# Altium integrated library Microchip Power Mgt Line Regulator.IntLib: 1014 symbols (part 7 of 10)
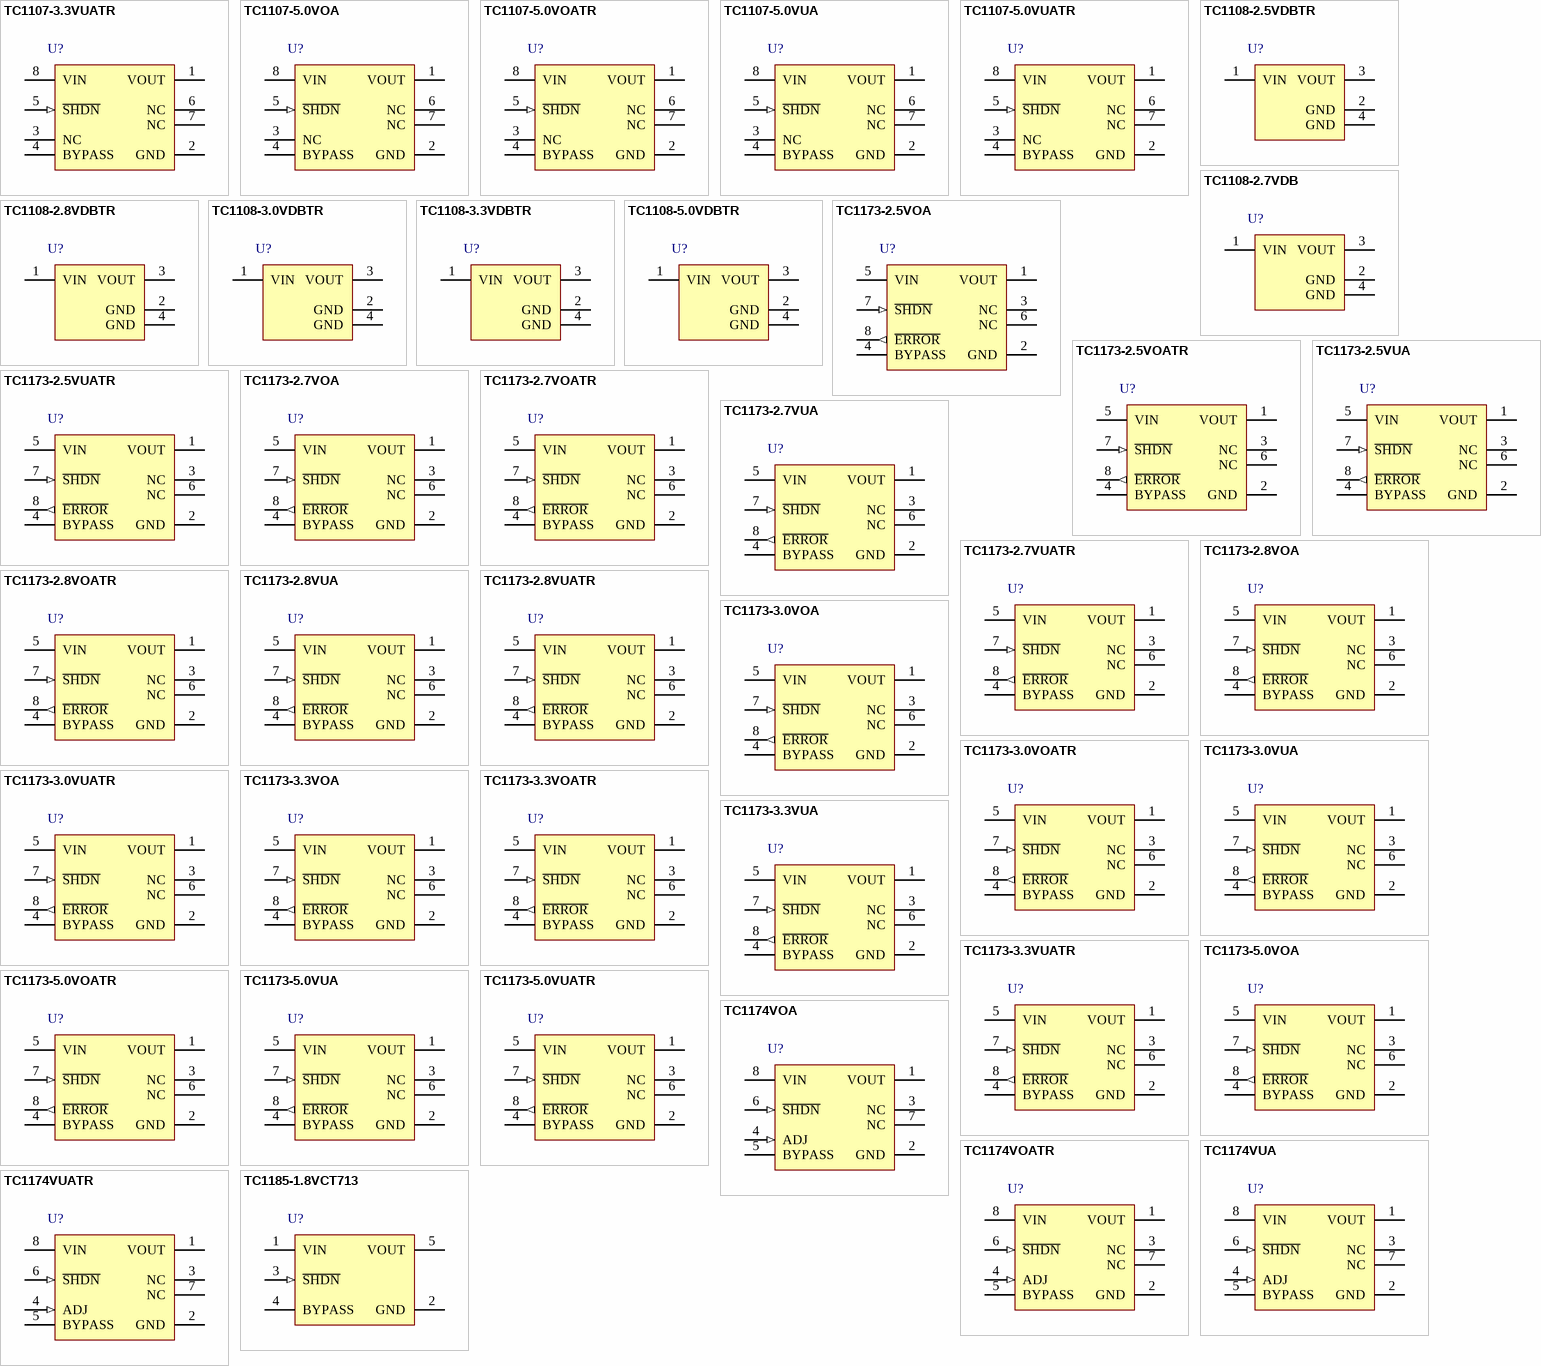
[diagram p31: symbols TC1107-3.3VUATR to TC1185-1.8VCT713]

## TC1173-3.0VOA
designator U?
300mA CMOS LDO with Shutdown Active-Low Error Output and Bypass, 8-Pin SOIC 150mil, Extended Temperature
footprint SOIC-OA8_N (SOIC, 8-Leads, Body 4.9x3.9mm, Pitch 1.27mm, IPC Medium Density)
footprint SOIC-OA8_L (SOIC, 8-Leads, Body 4.9x3.9mm, Pitch 1.27mm, IPC High Density)
footprint SOIC-OA8_M (SOIC, 8-Leads, Body 4.9x3.9mm, Pitch 1.27mm, IPC Low Density)
pins: 1 VOUT (power), 2 GND (power), 3 NC, 4 BYPASS, 5 VIN (power), 6 NC, 7 ~{SHDN} (in), 8 ~{ERROR} (out)

## TC1173-3.0VOATR
designator U?
300mA CMOS LDO with Shutdown Active-Low Error Output and Bypass, 8-Pin SOIC 150mil, Extended Temperature, Tape and Reel
footprint SOIC-OA8_N (SOIC, 8-Leads, Body 4.9x3.9mm, Pitch 1.27mm, IPC Medium Density)
footprint SOIC-OA8_L (SOIC, 8-Leads, Body 4.9x3.9mm, Pitch 1.27mm, IPC High Density)
footprint SOIC-OA8_M (SOIC, 8-Leads, Body 4.9x3.9mm, Pitch 1.27mm, IPC Low Density)
pins: 1 VOUT (power), 2 GND (power), 3 NC, 4 BYPASS, 5 VIN (power), 6 NC, 7 ~{SHDN} (in), 8 ~{ERROR} (out)

## TC1173-3.0VUA
designator U?
300mA CMOS LDO with Shutdown Active-Low Error Output and Bypass, 8-Pin MSOP, Extended Temperature
footprint MSOP-UA8_N (TSOP, 8-Leads, Body 3x3mm, Pitch 0.65mm, IPC Medium Density)
footprint MSOP-UA8_L (TSOP, 8-Leads, Body 3x3mm, Pitch 0.65mm, IPC High Density)
footprint MSOP-UA8_M (TSOP, 8-Leads, Body 3x3mm, Pitch 0.65mm, IPC Low Density)
pins: 1 VOUT (power), 2 GND (power), 3 NC, 4 BYPASS, 5 VIN (power), 6 NC, 7 ~{SHDN} (in), 8 ~{ERROR} (out)

## TC1173-3.0VUATR
designator U?
300mA CMOS LDO with Shutdown Active-Low Error Output and Bypass, 8-Pin MSOP, Extended Temperature, Tape and Reel
footprint MSOP-UA8_N (TSOP, 8-Leads, Body 3x3mm, Pitch 0.65mm, IPC Medium Density)
footprint MSOP-UA8_L (TSOP, 8-Leads, Body 3x3mm, Pitch 0.65mm, IPC High Density)
footprint MSOP-UA8_M (TSOP, 8-Leads, Body 3x3mm, Pitch 0.65mm, IPC Low Density)
pins: 1 VOUT (power), 2 GND (power), 3 NC, 4 BYPASS, 5 VIN (power), 6 NC, 7 ~{SHDN} (in), 8 ~{ERROR} (out)

## TC1173-3.3VOA
designator U?
300mA CMOS LDO with Shutdown Active-Low Error Output and Bypass, 8-Pin SOIC 150mil, Extended Temperature
footprint SOIC-OA8_N (SOIC, 8-Leads, Body 4.9x3.9mm, Pitch 1.27mm, IPC Medium Density)
footprint SOIC-OA8_L (SOIC, 8-Leads, Body 4.9x3.9mm, Pitch 1.27mm, IPC High Density)
footprint SOIC-OA8_M (SOIC, 8-Leads, Body 4.9x3.9mm, Pitch 1.27mm, IPC Low Density)
pins: 1 VOUT (power), 2 GND (power), 3 NC, 4 BYPASS, 5 VIN (power), 6 NC, 7 ~{SHDN} (in), 8 ~{ERROR} (out)

## TC1173-3.3VOATR
designator U?
300mA CMOS LDO with Shutdown Active-Low Error Output and Bypass, 8-Pin SOIC 150mil, Extended Temperature, Tape and Reel
footprint SOIC-OA8_N (SOIC, 8-Leads, Body 4.9x3.9mm, Pitch 1.27mm, IPC Medium Density)
footprint SOIC-OA8_L (SOIC, 8-Leads, Body 4.9x3.9mm, Pitch 1.27mm, IPC High Density)
footprint SOIC-OA8_M (SOIC, 8-Leads, Body 4.9x3.9mm, Pitch 1.27mm, IPC Low Density)
pins: 1 VOUT (power), 2 GND (power), 3 NC, 4 BYPASS, 5 VIN (power), 6 NC, 7 ~{SHDN} (in), 8 ~{ERROR} (out)

## TC1173-3.3VUA
designator U?
300mA CMOS LDO with Shutdown Active-Low Error Output and Bypass, 8-Pin MSOP, Extended Temperature
footprint MSOP-UA8_N (TSOP, 8-Leads, Body 3x3mm, Pitch 0.65mm, IPC Medium Density)
footprint MSOP-UA8_L (TSOP, 8-Leads, Body 3x3mm, Pitch 0.65mm, IPC High Density)
footprint MSOP-UA8_M (TSOP, 8-Leads, Body 3x3mm, Pitch 0.65mm, IPC Low Density)
pins: 1 VOUT (power), 2 GND (power), 3 NC, 4 BYPASS, 5 VIN (power), 6 NC, 7 ~{SHDN} (in), 8 ~{ERROR} (out)

## TC1173-3.3VUATR
designator U?
300mA CMOS LDO with Shutdown Active-Low Error Output and Bypass, 8-Pin MSOP, Extended Temperature, Tape and Reel
footprint MSOP-UA8_N (TSOP, 8-Leads, Body 3x3mm, Pitch 0.65mm, IPC Medium Density)
footprint MSOP-UA8_L (TSOP, 8-Leads, Body 3x3mm, Pitch 0.65mm, IPC High Density)
footprint MSOP-UA8_M (TSOP, 8-Leads, Body 3x3mm, Pitch 0.65mm, IPC Low Density)
pins: 1 VOUT (power), 2 GND (power), 3 NC, 4 BYPASS, 5 VIN (power), 6 NC, 7 ~{SHDN} (in), 8 ~{ERROR} (out)

## TC1173-5.0VOA
designator U?
300mA CMOS LDO with Shutdown Active-Low Error Output and Bypass, 8-Pin SOIC 150mil, Extended Temperature
footprint SOIC-OA8_N (SOIC, 8-Leads, Body 4.9x3.9mm, Pitch 1.27mm, IPC Medium Density)
footprint SOIC-OA8_L (SOIC, 8-Leads, Body 4.9x3.9mm, Pitch 1.27mm, IPC High Density)
footprint SOIC-OA8_M (SOIC, 8-Leads, Body 4.9x3.9mm, Pitch 1.27mm, IPC Low Density)
pins: 1 VOUT (power), 2 GND (power), 3 NC, 4 BYPASS, 5 VIN (power), 6 NC, 7 ~{SHDN} (in), 8 ~{ERROR} (out)

## TC1173-5.0VOATR
designator U?
300mA CMOS LDO with Shutdown Active-Low Error Output and Bypass, 8-Pin SOIC 150mil, Extended Temperature, Tape and Reel
footprint SOIC-OA8_N (SOIC, 8-Leads, Body 4.9x3.9mm, Pitch 1.27mm, IPC Medium Density)
footprint SOIC-OA8_L (SOIC, 8-Leads, Body 4.9x3.9mm, Pitch 1.27mm, IPC High Density)
footprint SOIC-OA8_M (SOIC, 8-Leads, Body 4.9x3.9mm, Pitch 1.27mm, IPC Low Density)
pins: 1 VOUT (power), 2 GND (power), 3 NC, 4 BYPASS, 5 VIN (power), 6 NC, 7 ~{SHDN} (in), 8 ~{ERROR} (out)

## TC1173-5.0VUA
designator U?
300mA CMOS LDO with Shutdown Active-Low Error Output and Bypass, 8-Pin MSOP, Extended Temperature
footprint MSOP-UA8_N (TSOP, 8-Leads, Body 3x3mm, Pitch 0.65mm, IPC Medium Density)
footprint MSOP-UA8_L (TSOP, 8-Leads, Body 3x3mm, Pitch 0.65mm, IPC High Density)
footprint MSOP-UA8_M (TSOP, 8-Leads, Body 3x3mm, Pitch 0.65mm, IPC Low Density)
pins: 1 VOUT (power), 2 GND (power), 3 NC, 4 BYPASS, 5 VIN (power), 6 NC, 7 ~{SHDN} (in), 8 ~{ERROR} (out)

## TC1173-5.0VUATR
designator U?
300mA CMOS LDO with Shutdown Active-Low Error Output and Bypass, 8-Pin MSOP, Extended Temperature, Tape and Reel
footprint MSOP-UA8_N (TSOP, 8-Leads, Body 3x3mm, Pitch 0.65mm, IPC Medium Density)
footprint MSOP-UA8_L (TSOP, 8-Leads, Body 3x3mm, Pitch 0.65mm, IPC High Density)
footprint MSOP-UA8_M (TSOP, 8-Leads, Body 3x3mm, Pitch 0.65mm, IPC Low Density)
pins: 1 VOUT (power), 2 GND (power), 3 NC, 4 BYPASS, 5 VIN (power), 6 NC, 7 ~{SHDN} (in), 8 ~{ERROR} (out)

## TC1174VOA
designator U?
300mA CMOS LDO with Shutdown and VREF Bypass, 8-Pin SOIC 150mil, Extended Temperature
footprint SOIC-OA8_N (SOIC, 8-Leads, Body 4.9x3.9mm, Pitch 1.27mm, IPC Medium Density)
footprint SOIC-OA8_L (SOIC, 8-Leads, Body 4.9x3.9mm, Pitch 1.27mm, IPC High Density)
footprint SOIC-OA8_M (SOIC, 8-Leads, Body 4.9x3.9mm, Pitch 1.27mm, IPC Low Density)
pins: 1 VOUT (power), 2 GND (power), 3 NC, 4 ADJ (in), 5 BYPASS, 6 ~{SHDN} (in), 7 NC, 8 VIN (power)

## TC1174VOATR
designator U?
300mA CMOS LDO with Shutdown and VREF Bypass, 8-Pin SOIC 150mil, Extended Temperature, Tape and Reel
footprint SOIC-OA8_N (SOIC, 8-Leads, Body 4.9x3.9mm, Pitch 1.27mm, IPC Medium Density)
footprint SOIC-OA8_L (SOIC, 8-Leads, Body 4.9x3.9mm, Pitch 1.27mm, IPC High Density)
footprint SOIC-OA8_M (SOIC, 8-Leads, Body 4.9x3.9mm, Pitch 1.27mm, IPC Low Density)
pins: 1 VOUT (power), 2 GND (power), 3 NC, 4 ADJ (in), 5 BYPASS, 6 ~{SHDN} (in), 7 NC, 8 VIN (power)

## TC1174VUA
designator U?
300mA CMOS LDO with Shutdown and VREF Bypass, 8-Pin MSOP, Extended Temperature
footprint MSOP-UA8_N (TSOP, 8-Leads, Body 3x3mm, Pitch 0.65mm, IPC Medium Density)
footprint MSOP-UA8_L (TSOP, 8-Leads, Body 3x3mm, Pitch 0.65mm, IPC High Density)
footprint MSOP-UA8_M (TSOP, 8-Leads, Body 3x3mm, Pitch 0.65mm, IPC Low Density)
pins: 1 VOUT (power), 2 GND (power), 3 NC, 4 ADJ (in), 5 BYPASS, 6 ~{SHDN} (in), 7 NC, 8 VIN (power)

## TC1174VUATR
designator U?
300mA CMOS LDO with Shutdown and VREF Bypass, 8-Pin MSOP, Extended Temperature, Tape and Reel
footprint MSOP-UA8_N (TSOP, 8-Leads, Body 3x3mm, Pitch 0.65mm, IPC Medium Density)
footprint MSOP-UA8_L (TSOP, 8-Leads, Body 3x3mm, Pitch 0.65mm, IPC High Density)
footprint MSOP-UA8_M (TSOP, 8-Leads, Body 3x3mm, Pitch 0.65mm, IPC Low Density)
pins: 1 VOUT (power), 2 GND (power), 3 NC, 4 ADJ (in), 5 BYPASS, 6 ~{SHDN} (in), 7 NC, 8 VIN (power)

## TC1185-1.8VCT713
designator U?
50 mA, 100 mA and 150 mA CMOS LDOs with Active-Low Shutdown and Reference Bypass, 5-Pin SOT-23, Extended Temperature, Tape and Reel
footprint SOT-23-CT5_N (SOT23, 5-Leads, Body 2.9x1.6mm, Pitch 0.95mm, Lead Span 2.7mm, IPC Medium Density)
footprint SOT-23-CT5_L (SOT23, 5-Leads, Body 2.9x1.6mm, Pitch 0.95mm, Lead Span 2.7mm, IPC High Density)
footprint SOT-23-CT5_M (SOT23, 5-Leads, Body 2.9x1.6mm, Pitch 0.95mm, Lead Span 2.7mm, IPC Low Density)
pins: 1 VIN (power), 2 GND (power), 3 ~{SHDN} (in), 4 BYPASS, 5 VOUT (power)

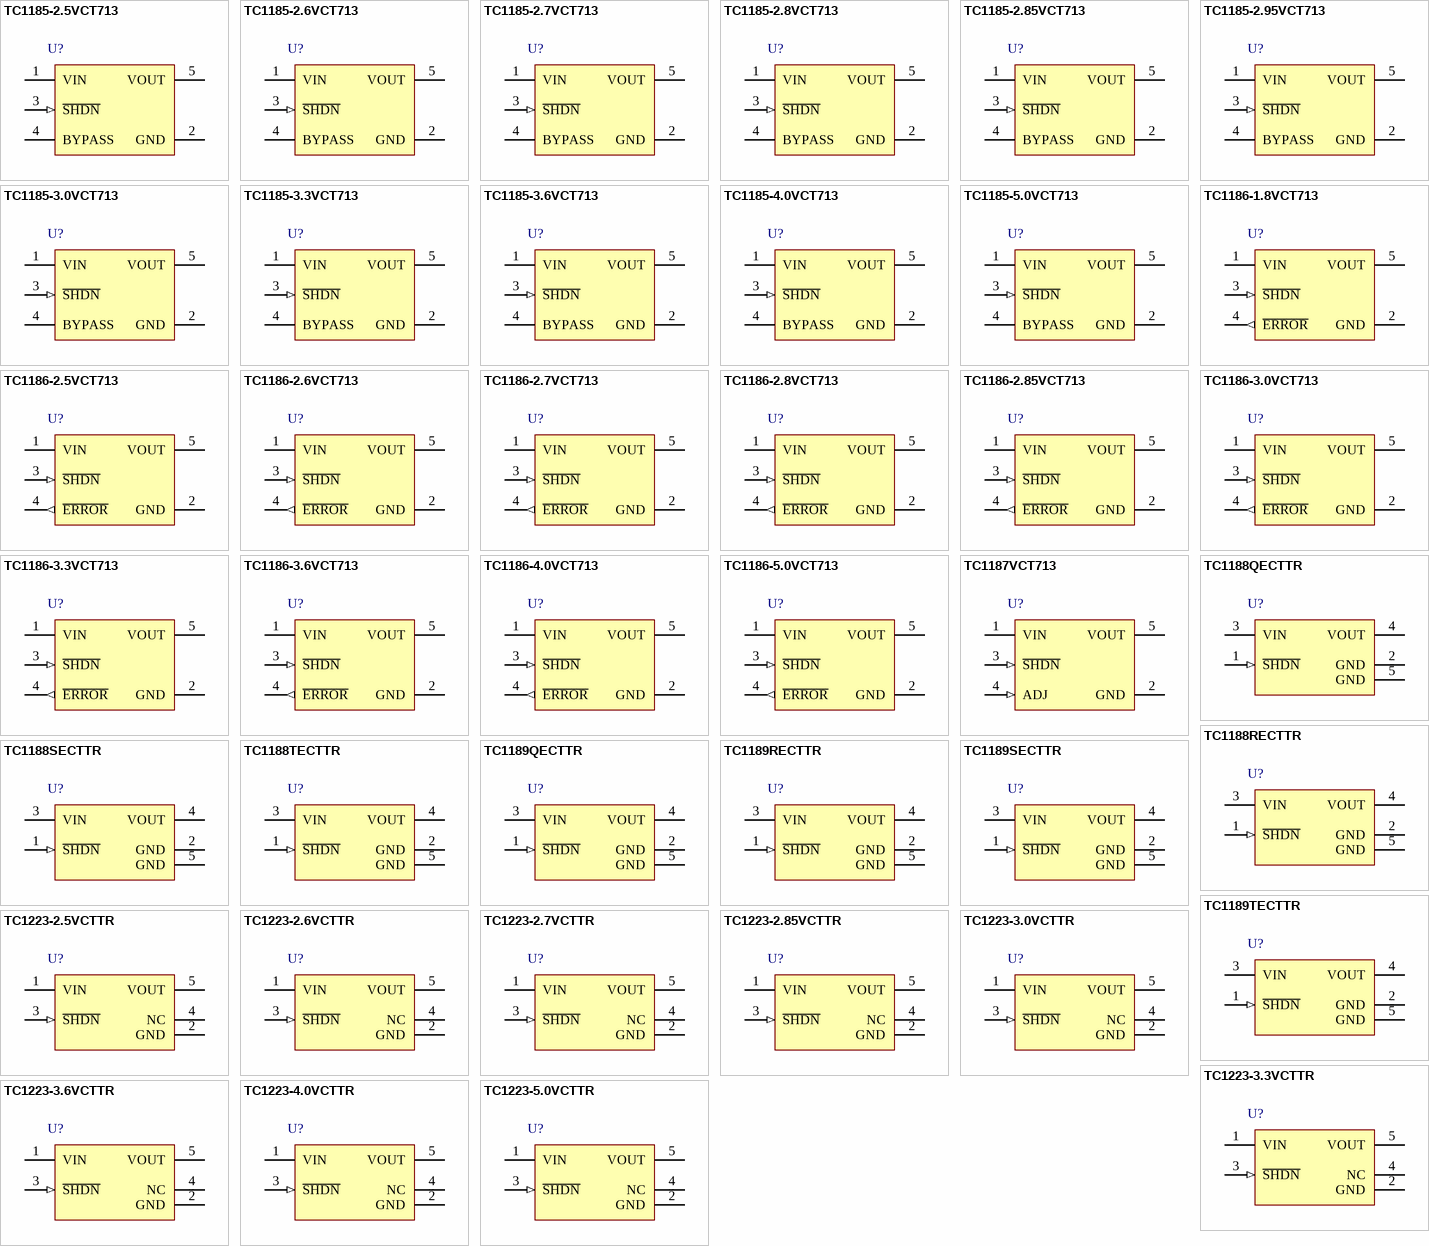
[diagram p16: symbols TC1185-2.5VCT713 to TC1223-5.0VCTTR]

## TC1185-2.5VCT713
designator U?
50 mA, 100 mA and 150 mA CMOS LDOs with Active-Low Shutdown and Reference Bypass, 5-Pin SOT-23, Extended Temperature, Tape and Reel
footprint SOT-23-CT5_N (SOT23, 5-Leads, Body 2.9x1.6mm, Pitch 0.95mm, Lead Span 2.7mm, IPC Medium Density)
footprint SOT-23-CT5_L (SOT23, 5-Leads, Body 2.9x1.6mm, Pitch 0.95mm, Lead Span 2.7mm, IPC High Density)
footprint SOT-23-CT5_M (SOT23, 5-Leads, Body 2.9x1.6mm, Pitch 0.95mm, Lead Span 2.7mm, IPC Low Density)
pins: 1 VIN (power), 2 GND (power), 3 ~{SHDN} (in), 4 BYPASS, 5 VOUT (power)

## TC1185-2.6VCT713
designator U?
50 mA, 100 mA and 150 mA CMOS LDOs with Active-Low Shutdown and Reference Bypass, 5-Pin SOT-23, Extended Temperature, Tape and Reel
footprint SOT-23-CT5_N (SOT23, 5-Leads, Body 2.9x1.6mm, Pitch 0.95mm, Lead Span 2.7mm, IPC Medium Density)
footprint SOT-23-CT5_L (SOT23, 5-Leads, Body 2.9x1.6mm, Pitch 0.95mm, Lead Span 2.7mm, IPC High Density)
footprint SOT-23-CT5_M (SOT23, 5-Leads, Body 2.9x1.6mm, Pitch 0.95mm, Lead Span 2.7mm, IPC Low Density)
pins: 1 VIN (power), 2 GND (power), 3 ~{SHDN} (in), 4 BYPASS, 5 VOUT (power)

## TC1185-2.7VCT713
designator U?
50 mA, 100 mA and 150 mA CMOS LDOs with Active-Low Shutdown and Reference Bypass, 5-Pin SOT-23, Extended Temperature, Tape and Reel
footprint SOT-23-CT5_N (SOT23, 5-Leads, Body 2.9x1.6mm, Pitch 0.95mm, Lead Span 2.7mm, IPC Medium Density)
footprint SOT-23-CT5_L (SOT23, 5-Leads, Body 2.9x1.6mm, Pitch 0.95mm, Lead Span 2.7mm, IPC High Density)
footprint SOT-23-CT5_M (SOT23, 5-Leads, Body 2.9x1.6mm, Pitch 0.95mm, Lead Span 2.7mm, IPC Low Density)
pins: 1 VIN (power), 2 GND (power), 3 ~{SHDN} (in), 4 BYPASS, 5 VOUT (power)

## TC1185-2.8VCT713
designator U?
50 mA, 100 mA and 150 mA CMOS LDOs with Active-Low Shutdown and Reference Bypass, 5-Pin SOT-23, Extended Temperature, Tape and Reel
footprint SOT-23-CT5_N (SOT23, 5-Leads, Body 2.9x1.6mm, Pitch 0.95mm, Lead Span 2.7mm, IPC Medium Density)
footprint SOT-23-CT5_L (SOT23, 5-Leads, Body 2.9x1.6mm, Pitch 0.95mm, Lead Span 2.7mm, IPC High Density)
footprint SOT-23-CT5_M (SOT23, 5-Leads, Body 2.9x1.6mm, Pitch 0.95mm, Lead Span 2.7mm, IPC Low Density)
pins: 1 VIN (power), 2 GND (power), 3 ~{SHDN} (in), 4 BYPASS, 5 VOUT (power)

## TC1185-2.85VCT713
designator U?
50 mA, 100 mA and 150 mA CMOS LDOs with Active-Low Shutdown and Reference Bypass, 5-Pin SOT-23, Extended Temperature, Tape and Reel
footprint SOT-23-CT5_N (SOT23, 5-Leads, Body 2.9x1.6mm, Pitch 0.95mm, Lead Span 2.7mm, IPC Medium Density)
footprint SOT-23-CT5_L (SOT23, 5-Leads, Body 2.9x1.6mm, Pitch 0.95mm, Lead Span 2.7mm, IPC High Density)
footprint SOT-23-CT5_M (SOT23, 5-Leads, Body 2.9x1.6mm, Pitch 0.95mm, Lead Span 2.7mm, IPC Low Density)
pins: 1 VIN (power), 2 GND (power), 3 ~{SHDN} (in), 4 BYPASS, 5 VOUT (power)

## TC1185-2.95VCT713
designator U?
50 mA, 100 mA and 150 mA CMOS LDOs with Active-Low Shutdown and Reference Bypass, 5-Pin SOT-23, Extended Temperature, Tape and Reel
footprint SOT-23-CT5_N (SOT23, 5-Leads, Body 2.9x1.6mm, Pitch 0.95mm, Lead Span 2.7mm, IPC Medium Density)
footprint SOT-23-CT5_L (SOT23, 5-Leads, Body 2.9x1.6mm, Pitch 0.95mm, Lead Span 2.7mm, IPC High Density)
footprint SOT-23-CT5_M (SOT23, 5-Leads, Body 2.9x1.6mm, Pitch 0.95mm, Lead Span 2.7mm, IPC Low Density)
pins: 1 VIN (power), 2 GND (power), 3 ~{SHDN} (in), 4 BYPASS, 5 VOUT (power)

## TC1185-3.0VCT713
designator U?
50 mA, 100 mA and 150 mA CMOS LDOs with Active-Low Shutdown and Reference Bypass, 5-Pin SOT-23, Extended Temperature, Tape and Reel
footprint SOT-23-CT5_N (SOT23, 5-Leads, Body 2.9x1.6mm, Pitch 0.95mm, Lead Span 2.7mm, IPC Medium Density)
footprint SOT-23-CT5_L (SOT23, 5-Leads, Body 2.9x1.6mm, Pitch 0.95mm, Lead Span 2.7mm, IPC High Density)
footprint SOT-23-CT5_M (SOT23, 5-Leads, Body 2.9x1.6mm, Pitch 0.95mm, Lead Span 2.7mm, IPC Low Density)
pins: 1 VIN (power), 2 GND (power), 3 ~{SHDN} (in), 4 BYPASS, 5 VOUT (power)

## TC1185-3.3VCT713
designator U?
50 mA, 100 mA and 150 mA CMOS LDOs with Active-Low Shutdown and Reference Bypass, 5-Pin SOT-23, Extended Temperature, Tape and Reel
footprint SOT-23-CT5_N (SOT23, 5-Leads, Body 2.9x1.6mm, Pitch 0.95mm, Lead Span 2.7mm, IPC Medium Density)
footprint SOT-23-CT5_L (SOT23, 5-Leads, Body 2.9x1.6mm, Pitch 0.95mm, Lead Span 2.7mm, IPC High Density)
footprint SOT-23-CT5_M (SOT23, 5-Leads, Body 2.9x1.6mm, Pitch 0.95mm, Lead Span 2.7mm, IPC Low Density)
pins: 1 VIN (power), 2 GND (power), 3 ~{SHDN} (in), 4 BYPASS, 5 VOUT (power)

## TC1185-3.6VCT713
designator U?
50 mA, 100 mA and 150 mA CMOS LDOs with Active-Low Shutdown and Reference Bypass, 5-Pin SOT-23, Extended Temperature, Tape and Reel
footprint SOT-23-CT5_N (SOT23, 5-Leads, Body 2.9x1.6mm, Pitch 0.95mm, Lead Span 2.7mm, IPC Medium Density)
footprint SOT-23-CT5_L (SOT23, 5-Leads, Body 2.9x1.6mm, Pitch 0.95mm, Lead Span 2.7mm, IPC High Density)
footprint SOT-23-CT5_M (SOT23, 5-Leads, Body 2.9x1.6mm, Pitch 0.95mm, Lead Span 2.7mm, IPC Low Density)
pins: 1 VIN (power), 2 GND (power), 3 ~{SHDN} (in), 4 BYPASS, 5 VOUT (power)

## TC1185-4.0VCT713
designator U?
50 mA, 100 mA and 150 mA CMOS LDOs with Active-Low Shutdown and Reference Bypass, 5-Pin SOT-23, Extended Temperature, Tape and Reel
footprint SOT-23-CT5_N (SOT23, 5-Leads, Body 2.9x1.6mm, Pitch 0.95mm, Lead Span 2.7mm, IPC Medium Density)
footprint SOT-23-CT5_L (SOT23, 5-Leads, Body 2.9x1.6mm, Pitch 0.95mm, Lead Span 2.7mm, IPC High Density)
footprint SOT-23-CT5_M (SOT23, 5-Leads, Body 2.9x1.6mm, Pitch 0.95mm, Lead Span 2.7mm, IPC Low Density)
pins: 1 VIN (power), 2 GND (power), 3 ~{SHDN} (in), 4 BYPASS, 5 VOUT (power)

## TC1185-5.0VCT713
designator U?
50 mA, 100 mA and 150 mA CMOS LDOs with Active-Low Shutdown and Reference Bypass, 5-Pin SOT-23, Extended Temperature, Tape and Reel
footprint SOT-23-CT5_N (SOT23, 5-Leads, Body 2.9x1.6mm, Pitch 0.95mm, Lead Span 2.7mm, IPC Medium Density)
footprint SOT-23-CT5_L (SOT23, 5-Leads, Body 2.9x1.6mm, Pitch 0.95mm, Lead Span 2.7mm, IPC High Density)
footprint SOT-23-CT5_M (SOT23, 5-Leads, Body 2.9x1.6mm, Pitch 0.95mm, Lead Span 2.7mm, IPC Low Density)
pins: 1 VIN (power), 2 GND (power), 3 ~{SHDN} (in), 4 BYPASS, 5 VOUT (power)

## TC1186-1.8VCT713
designator U?
50 mA, 100 mA and 150 mA CMOS LDOs with Shutdown and Active-Low Error Output, 5-Pin SOT-23, Extended Temperature, Tape and Reel
footprint SOT-23-CT5_N (SOT23, 5-Leads, Body 2.9x1.6mm, Pitch 0.95mm, Lead Span 2.7mm, IPC Medium Density)
footprint SOT-23-CT5_L (SOT23, 5-Leads, Body 2.9x1.6mm, Pitch 0.95mm, Lead Span 2.7mm, IPC High Density)
footprint SOT-23-CT5_M (SOT23, 5-Leads, Body 2.9x1.6mm, Pitch 0.95mm, Lead Span 2.7mm, IPC Low Density)
pins: 1 VIN (power), 2 GND (power), 3 ~{SHDN} (in), 4 ~{ERROR} (out), 5 VOUT (power)

## TC1186-2.5VCT713
designator U?
50 mA, 100 mA and 150 mA CMOS LDOs with Shutdown and Active-Low Error Output, 5-Pin SOT-23, Extended Temperature, Tape and Reel
footprint SOT-23-CT5_N (SOT23, 5-Leads, Body 2.9x1.6mm, Pitch 0.95mm, Lead Span 2.7mm, IPC Medium Density)
footprint SOT-23-CT5_L (SOT23, 5-Leads, Body 2.9x1.6mm, Pitch 0.95mm, Lead Span 2.7mm, IPC High Density)
footprint SOT-23-CT5_M (SOT23, 5-Leads, Body 2.9x1.6mm, Pitch 0.95mm, Lead Span 2.7mm, IPC Low Density)
pins: 1 VIN (power), 2 GND (power), 3 ~{SHDN} (in), 4 ~{ERROR} (out), 5 VOUT (power)

## TC1186-2.6VCT713
designator U?
50 mA, 100 mA and 150 mA CMOS LDOs with Shutdown and Active-Low Error Output, 5-Pin SOT-23, Extended Temperature, Tape and Reel
footprint SOT-23-CT5_N (SOT23, 5-Leads, Body 2.9x1.6mm, Pitch 0.95mm, Lead Span 2.7mm, IPC Medium Density)
footprint SOT-23-CT5_L (SOT23, 5-Leads, Body 2.9x1.6mm, Pitch 0.95mm, Lead Span 2.7mm, IPC High Density)
footprint SOT-23-CT5_M (SOT23, 5-Leads, Body 2.9x1.6mm, Pitch 0.95mm, Lead Span 2.7mm, IPC Low Density)
pins: 1 VIN (power), 2 GND (power), 3 ~{SHDN} (in), 4 ~{ERROR} (out), 5 VOUT (power)

## TC1186-2.7VCT713
designator U?
50 mA, 100 mA and 150 mA CMOS LDOs with Shutdown and Active-Low Error Output, 5-Pin SOT-23, Extended Temperature, Tape and Reel
footprint SOT-23-CT5_N (SOT23, 5-Leads, Body 2.9x1.6mm, Pitch 0.95mm, Lead Span 2.7mm, IPC Medium Density)
footprint SOT-23-CT5_L (SOT23, 5-Leads, Body 2.9x1.6mm, Pitch 0.95mm, Lead Span 2.7mm, IPC High Density)
footprint SOT-23-CT5_M (SOT23, 5-Leads, Body 2.9x1.6mm, Pitch 0.95mm, Lead Span 2.7mm, IPC Low Density)
pins: 1 VIN (power), 2 GND (power), 3 ~{SHDN} (in), 4 ~{ERROR} (out), 5 VOUT (power)

## TC1186-2.8VCT713
designator U?
50 mA, 100 mA and 150 mA CMOS LDOs with Shutdown and Active-Low Error Output, 5-Pin SOT-23, Extended Temperature, Tape and Reel
footprint SOT-23-CT5_N (SOT23, 5-Leads, Body 2.9x1.6mm, Pitch 0.95mm, Lead Span 2.7mm, IPC Medium Density)
footprint SOT-23-CT5_L (SOT23, 5-Leads, Body 2.9x1.6mm, Pitch 0.95mm, Lead Span 2.7mm, IPC High Density)
footprint SOT-23-CT5_M (SOT23, 5-Leads, Body 2.9x1.6mm, Pitch 0.95mm, Lead Span 2.7mm, IPC Low Density)
pins: 1 VIN (power), 2 GND (power), 3 ~{SHDN} (in), 4 ~{ERROR} (out), 5 VOUT (power)

## TC1186-2.85VCT713
designator U?
50 mA, 100 mA and 150 mA CMOS LDOs with Shutdown and Active-Low Error Output, 5-Pin SOT-23, Extended Temperature, Tape and Reel
footprint SOT-23-CT5_N (SOT23, 5-Leads, Body 2.9x1.6mm, Pitch 0.95mm, Lead Span 2.7mm, IPC Medium Density)
footprint SOT-23-CT5_L (SOT23, 5-Leads, Body 2.9x1.6mm, Pitch 0.95mm, Lead Span 2.7mm, IPC High Density)
footprint SOT-23-CT5_M (SOT23, 5-Leads, Body 2.9x1.6mm, Pitch 0.95mm, Lead Span 2.7mm, IPC Low Density)
pins: 1 VIN (power), 2 GND (power), 3 ~{SHDN} (in), 4 ~{ERROR} (out), 5 VOUT (power)

## TC1186-3.0VCT713
designator U?
50 mA, 100 mA and 150 mA CMOS LDOs with Shutdown and Active-Low Error Output, 5-Pin SOT-23, Extended Temperature, Tape and Reel
footprint SOT-23-CT5_N (SOT23, 5-Leads, Body 2.9x1.6mm, Pitch 0.95mm, Lead Span 2.7mm, IPC Medium Density)
footprint SOT-23-CT5_L (SOT23, 5-Leads, Body 2.9x1.6mm, Pitch 0.95mm, Lead Span 2.7mm, IPC High Density)
footprint SOT-23-CT5_M (SOT23, 5-Leads, Body 2.9x1.6mm, Pitch 0.95mm, Lead Span 2.7mm, IPC Low Density)
pins: 1 VIN (power), 2 GND (power), 3 ~{SHDN} (in), 4 ~{ERROR} (out), 5 VOUT (power)

## TC1186-3.3VCT713
designator U?
50 mA, 100 mA and 150 mA CMOS LDOs with Shutdown and Active-Low Error Output, 5-Pin SOT-23, Extended Temperature, Tape and Reel
footprint SOT-23-CT5_N (SOT23, 5-Leads, Body 2.9x1.6mm, Pitch 0.95mm, Lead Span 2.7mm, IPC Medium Density)
footprint SOT-23-CT5_L (SOT23, 5-Leads, Body 2.9x1.6mm, Pitch 0.95mm, Lead Span 2.7mm, IPC High Density)
footprint SOT-23-CT5_M (SOT23, 5-Leads, Body 2.9x1.6mm, Pitch 0.95mm, Lead Span 2.7mm, IPC Low Density)
pins: 1 VIN (power), 2 GND (power), 3 ~{SHDN} (in), 4 ~{ERROR} (out), 5 VOUT (power)

## TC1186-3.6VCT713
designator U?
50 mA, 100 mA and 150 mA CMOS LDOs with Shutdown and Active-Low Error Output, 5-Pin SOT-23, Extended Temperature, Tape and Reel
footprint SOT-23-CT5_N (SOT23, 5-Leads, Body 2.9x1.6mm, Pitch 0.95mm, Lead Span 2.7mm, IPC Medium Density)
footprint SOT-23-CT5_L (SOT23, 5-Leads, Body 2.9x1.6mm, Pitch 0.95mm, Lead Span 2.7mm, IPC High Density)
footprint SOT-23-CT5_M (SOT23, 5-Leads, Body 2.9x1.6mm, Pitch 0.95mm, Lead Span 2.7mm, IPC Low Density)
pins: 1 VIN (power), 2 GND (power), 3 ~{SHDN} (in), 4 ~{ERROR} (out), 5 VOUT (power)

## TC1186-4.0VCT713
designator U?
50 mA, 100 mA and 150 mA CMOS LDOs with Shutdown and Active-Low Error Output, 5-Pin SOT-23, Extended Temperature, Tape and Reel
footprint SOT-23-CT5_N (SOT23, 5-Leads, Body 2.9x1.6mm, Pitch 0.95mm, Lead Span 2.7mm, IPC Medium Density)
footprint SOT-23-CT5_L (SOT23, 5-Leads, Body 2.9x1.6mm, Pitch 0.95mm, Lead Span 2.7mm, IPC High Density)
footprint SOT-23-CT5_M (SOT23, 5-Leads, Body 2.9x1.6mm, Pitch 0.95mm, Lead Span 2.7mm, IPC Low Density)
pins: 1 VIN (power), 2 GND (power), 3 ~{SHDN} (in), 4 ~{ERROR} (out), 5 VOUT (power)

## TC1186-5.0VCT713
designator U?
50 mA, 100 mA and 150 mA CMOS LDOs with Shutdown and Active-Low Error Output, 5-Pin SOT-23, Extended Temperature, Tape and Reel
footprint SOT-23-CT5_N (SOT23, 5-Leads, Body 2.9x1.6mm, Pitch 0.95mm, Lead Span 2.7mm, IPC Medium Density)
footprint SOT-23-CT5_L (SOT23, 5-Leads, Body 2.9x1.6mm, Pitch 0.95mm, Lead Span 2.7mm, IPC High Density)
footprint SOT-23-CT5_M (SOT23, 5-Leads, Body 2.9x1.6mm, Pitch 0.95mm, Lead Span 2.7mm, IPC Low Density)
pins: 1 VIN (power), 2 GND (power), 3 ~{SHDN} (in), 4 ~{ERROR} (out), 5 VOUT (power)

## TC1187VCT713
designator U?
50mA, 100mA and 150mA Adjustable CMOS LDOs with Shutdown, 5-Pin SOT-23, Extended Temperature, Tape and Reel
footprint SOT-23-CT5_N (SOT23, 5-Leads, Body 2.9x1.6mm, Pitch 0.95mm, Lead Span 2.7mm, IPC Medium Density)
footprint SOT-23-CT5_L (SOT23, 5-Leads, Body 2.9x1.6mm, Pitch 0.95mm, Lead Span 2.7mm, IPC High Density)
footprint SOT-23-CT5_M (SOT23, 5-Leads, Body 2.9x1.6mm, Pitch 0.95mm, Lead Span 2.7mm, IPC Low Density)
pins: 1 VIN (power), 2 GND (power), 3 ~{SHDN} (in), 4 ADJ (in), 5 VOUT (power)

## TC1188QECTTR
designator U?
MAX8863/64 Pin Compatible, Low Dropout, 120 mA Linear Regulators, 5-Pin SOT-23, Industrial Temperature, Tape and Reel
footprint SOT-23-CT5_N (SOT23, 5-Leads, Body 2.9x1.6mm, Pitch 0.95mm, Lead Span 2.7mm, IPC Medium Density)
footprint SOT-23-CT5_L (SOT23, 5-Leads, Body 2.9x1.6mm, Pitch 0.95mm, Lead Span 2.7mm, IPC High Density)
footprint SOT-23-CT5_M (SOT23, 5-Leads, Body 2.9x1.6mm, Pitch 0.95mm, Lead Span 2.7mm, IPC Low Density)
pins: 1 ~{SHDN} (in), 2 GND (power), 3 VIN (power), 4 VOUT (power), 5 GND (power)

## TC1188RECTTR
designator U?
MAX8863/64 Pin Compatible, Low Dropout, 120 mA Linear Regulators, 5-Pin SOT-23, Industrial Temperature, Tape and Reel
footprint SOT-23-CT5_N (SOT23, 5-Leads, Body 2.9x1.6mm, Pitch 0.95mm, Lead Span 2.7mm, IPC Medium Density)
footprint SOT-23-CT5_L (SOT23, 5-Leads, Body 2.9x1.6mm, Pitch 0.95mm, Lead Span 2.7mm, IPC High Density)
footprint SOT-23-CT5_M (SOT23, 5-Leads, Body 2.9x1.6mm, Pitch 0.95mm, Lead Span 2.7mm, IPC Low Density)
pins: 1 ~{SHDN} (in), 2 GND (power), 3 VIN (power), 4 VOUT (power), 5 GND (power)

## TC1188SECTTR
designator U?
MAX8863/64 Pin Compatible, Low Dropout, 120 mA Linear Regulators, 5-Pin SOT-23, Industrial Temperature, Tape and Reel
footprint SOT-23-CT5_N (SOT23, 5-Leads, Body 2.9x1.6mm, Pitch 0.95mm, Lead Span 2.7mm, IPC Medium Density)
footprint SOT-23-CT5_L (SOT23, 5-Leads, Body 2.9x1.6mm, Pitch 0.95mm, Lead Span 2.7mm, IPC High Density)
footprint SOT-23-CT5_M (SOT23, 5-Leads, Body 2.9x1.6mm, Pitch 0.95mm, Lead Span 2.7mm, IPC Low Density)
pins: 1 ~{SHDN} (in), 2 GND (power), 3 VIN (power), 4 VOUT (power), 5 GND (power)

## TC1188TECTTR
designator U?
MAX8863/64 Pin Compatible, Low Dropout, 120 mA Linear Regulators, 5-Pin SOT-23, Industrial Temperature, Tape and Reel
footprint SOT-23-CT5_N (SOT23, 5-Leads, Body 2.9x1.6mm, Pitch 0.95mm, Lead Span 2.7mm, IPC Medium Density)
footprint SOT-23-CT5_L (SOT23, 5-Leads, Body 2.9x1.6mm, Pitch 0.95mm, Lead Span 2.7mm, IPC High Density)
footprint SOT-23-CT5_M (SOT23, 5-Leads, Body 2.9x1.6mm, Pitch 0.95mm, Lead Span 2.7mm, IPC Low Density)
pins: 1 ~{SHDN} (in), 2 GND (power), 3 VIN (power), 4 VOUT (power), 5 GND (power)

## TC1189QECTTR
designator U?
MAX8863/64 Pin Compatible, Low Dropout, 120 mA Linear Regulators, 5-Pin SOT-23, Industrial Temperature, Tape and Reel
footprint SOT-23-CT5_N (SOT23, 5-Leads, Body 2.9x1.6mm, Pitch 0.95mm, Lead Span 2.7mm, IPC Medium Density)
footprint SOT-23-CT5_L (SOT23, 5-Leads, Body 2.9x1.6mm, Pitch 0.95mm, Lead Span 2.7mm, IPC High Density)
footprint SOT-23-CT5_M (SOT23, 5-Leads, Body 2.9x1.6mm, Pitch 0.95mm, Lead Span 2.7mm, IPC Low Density)
pins: 1 ~{SHDN} (in), 2 GND (power), 3 VIN (power), 4 VOUT (power), 5 GND (power)

## TC1189RECTTR
designator U?
MAX8863/64 Pin Compatible, Low Dropout, 120 mA Linear Regulators, 5-Pin SOT-23, Industrial Temperature, Tape and Reel
footprint SOT-23-CT5_N (SOT23, 5-Leads, Body 2.9x1.6mm, Pitch 0.95mm, Lead Span 2.7mm, IPC Medium Density)
footprint SOT-23-CT5_L (SOT23, 5-Leads, Body 2.9x1.6mm, Pitch 0.95mm, Lead Span 2.7mm, IPC High Density)
footprint SOT-23-CT5_M (SOT23, 5-Leads, Body 2.9x1.6mm, Pitch 0.95mm, Lead Span 2.7mm, IPC Low Density)
pins: 1 ~{SHDN} (in), 2 GND (power), 3 VIN (power), 4 VOUT (power), 5 GND (power)

## TC1189SECTTR
designator U?
MAX8863/64 Pin Compatible, Low Dropout, 120 mA Linear Regulators, 5-Pin SOT-23, Industrial Temperature, Tape and Reel
footprint SOT-23-CT5_N (SOT23, 5-Leads, Body 2.9x1.6mm, Pitch 0.95mm, Lead Span 2.7mm, IPC Medium Density)
footprint SOT-23-CT5_L (SOT23, 5-Leads, Body 2.9x1.6mm, Pitch 0.95mm, Lead Span 2.7mm, IPC High Density)
footprint SOT-23-CT5_M (SOT23, 5-Leads, Body 2.9x1.6mm, Pitch 0.95mm, Lead Span 2.7mm, IPC Low Density)
pins: 1 ~{SHDN} (in), 2 GND (power), 3 VIN (power), 4 VOUT (power), 5 GND (power)

## TC1189TECTTR
designator U?
MAX8863/64 Pin Compatible, Low Dropout, 120 mA Linear Regulators, 5-Pin SOT-23, Industrial Temperature, Tape and Reel
footprint SOT-23-CT5_N (SOT23, 5-Leads, Body 2.9x1.6mm, Pitch 0.95mm, Lead Span 2.7mm, IPC Medium Density)
footprint SOT-23-CT5_L (SOT23, 5-Leads, Body 2.9x1.6mm, Pitch 0.95mm, Lead Span 2.7mm, IPC High Density)
footprint SOT-23-CT5_M (SOT23, 5-Leads, Body 2.9x1.6mm, Pitch 0.95mm, Lead Span 2.7mm, IPC Low Density)
pins: 1 ~{SHDN} (in), 2 GND (power), 3 VIN (power), 4 VOUT (power), 5 GND (power)

## TC1223-2.5VCTTR
designator U?
50mA and 100mA CMOS LDOs with Shutdown, 5-Pin SOT-23, Extended Temperature, Tape and Reel
footprint SOT-23-CT5_N (SOT23, 5-Leads, Body 2.9x1.6mm, Pitch 0.95mm, Lead Span 2.7mm, IPC Medium Density)
footprint SOT-23-CT5_L (SOT23, 5-Leads, Body 2.9x1.6mm, Pitch 0.95mm, Lead Span 2.7mm, IPC High Density)
footprint SOT-23-CT5_M (SOT23, 5-Leads, Body 2.9x1.6mm, Pitch 0.95mm, Lead Span 2.7mm, IPC Low Density)
pins: 1 VIN (power), 2 GND (power), 3 ~{SHDN} (in), 4 NC, 5 VOUT (power)

## TC1223-2.6VCTTR
designator U?
50mA and 100mA CMOS LDOs with Shutdown, 5-Pin SOT-23, Extended Temperature, Tape and Reel
footprint SOT-23-CT5_N (SOT23, 5-Leads, Body 2.9x1.6mm, Pitch 0.95mm, Lead Span 2.7mm, IPC Medium Density)
footprint SOT-23-CT5_L (SOT23, 5-Leads, Body 2.9x1.6mm, Pitch 0.95mm, Lead Span 2.7mm, IPC High Density)
footprint SOT-23-CT5_M (SOT23, 5-Leads, Body 2.9x1.6mm, Pitch 0.95mm, Lead Span 2.7mm, IPC Low Density)
pins: 1 VIN (power), 2 GND (power), 3 ~{SHDN} (in), 4 NC, 5 VOUT (power)

## TC1223-2.7VCTTR
designator U?
50mA and 100mA CMOS LDOs with Shutdown, 5-Pin SOT-23, Extended Temperature, Tape and Reel
footprint SOT-23-CT5_N (SOT23, 5-Leads, Body 2.9x1.6mm, Pitch 0.95mm, Lead Span 2.7mm, IPC Medium Density)
footprint SOT-23-CT5_L (SOT23, 5-Leads, Body 2.9x1.6mm, Pitch 0.95mm, Lead Span 2.7mm, IPC High Density)
footprint SOT-23-CT5_M (SOT23, 5-Leads, Body 2.9x1.6mm, Pitch 0.95mm, Lead Span 2.7mm, IPC Low Density)
pins: 1 VIN (power), 2 GND (power), 3 ~{SHDN} (in), 4 NC, 5 VOUT (power)

## TC1223-2.85VCTTR
designator U?
50mA and 100mA CMOS LDOs with Shutdown, 5-Pin SOT-23, Extended Temperature, Tape and Reel
footprint SOT-23-CT5_N (SOT23, 5-Leads, Body 2.9x1.6mm, Pitch 0.95mm, Lead Span 2.7mm, IPC Medium Density)
footprint SOT-23-CT5_L (SOT23, 5-Leads, Body 2.9x1.6mm, Pitch 0.95mm, Lead Span 2.7mm, IPC High Density)
footprint SOT-23-CT5_M (SOT23, 5-Leads, Body 2.9x1.6mm, Pitch 0.95mm, Lead Span 2.7mm, IPC Low Density)
pins: 1 VIN (power), 2 GND (power), 3 ~{SHDN} (in), 4 NC, 5 VOUT (power)

## TC1223-3.0VCTTR
designator U?
50mA and 100mA CMOS LDOs with Shutdown, 5-Pin SOT-23, Extended Temperature, Tape and Reel
footprint SOT-23-CT5_N (SOT23, 5-Leads, Body 2.9x1.6mm, Pitch 0.95mm, Lead Span 2.7mm, IPC Medium Density)
footprint SOT-23-CT5_L (SOT23, 5-Leads, Body 2.9x1.6mm, Pitch 0.95mm, Lead Span 2.7mm, IPC High Density)
footprint SOT-23-CT5_M (SOT23, 5-Leads, Body 2.9x1.6mm, Pitch 0.95mm, Lead Span 2.7mm, IPC Low Density)
pins: 1 VIN (power), 2 GND (power), 3 ~{SHDN} (in), 4 NC, 5 VOUT (power)

## TC1223-3.3VCTTR
designator U?
50mA and 100mA CMOS LDOs with Shutdown, 5-Pin SOT-23, Extended Temperature, Tape and Reel
footprint SOT-23-CT5_N (SOT23, 5-Leads, Body 2.9x1.6mm, Pitch 0.95mm, Lead Span 2.7mm, IPC Medium Density)
footprint SOT-23-CT5_L (SOT23, 5-Leads, Body 2.9x1.6mm, Pitch 0.95mm, Lead Span 2.7mm, IPC High Density)
footprint SOT-23-CT5_M (SOT23, 5-Leads, Body 2.9x1.6mm, Pitch 0.95mm, Lead Span 2.7mm, IPC Low Density)
pins: 1 VIN (power), 2 GND (power), 3 ~{SHDN} (in), 4 NC, 5 VOUT (power)

## TC1223-3.6VCTTR
designator U?
50mA and 100mA CMOS LDOs with Shutdown, 5-Pin SOT-23, Extended Temperature, Tape and Reel
footprint SOT-23-CT5_N (SOT23, 5-Leads, Body 2.9x1.6mm, Pitch 0.95mm, Lead Span 2.7mm, IPC Medium Density)
footprint SOT-23-CT5_L (SOT23, 5-Leads, Body 2.9x1.6mm, Pitch 0.95mm, Lead Span 2.7mm, IPC High Density)
footprint SOT-23-CT5_M (SOT23, 5-Leads, Body 2.9x1.6mm, Pitch 0.95mm, Lead Span 2.7mm, IPC Low Density)
pins: 1 VIN (power), 2 GND (power), 3 ~{SHDN} (in), 4 NC, 5 VOUT (power)

## TC1223-4.0VCTTR
designator U?
50mA and 100mA CMOS LDOs with Shutdown, 5-Pin SOT-23, Extended Temperature, Tape and Reel
footprint SOT-23-CT5_N (SOT23, 5-Leads, Body 2.9x1.6mm, Pitch 0.95mm, Lead Span 2.7mm, IPC Medium Density)
footprint SOT-23-CT5_L (SOT23, 5-Leads, Body 2.9x1.6mm, Pitch 0.95mm, Lead Span 2.7mm, IPC High Density)
footprint SOT-23-CT5_M (SOT23, 5-Leads, Body 2.9x1.6mm, Pitch 0.95mm, Lead Span 2.7mm, IPC Low Density)
pins: 1 VIN (power), 2 GND (power), 3 ~{SHDN} (in), 4 NC, 5 VOUT (power)

## TC1223-5.0VCTTR
designator U?
50mA and 100mA CMOS LDOs with Shutdown, 5-Pin SOT-23, Extended Temperature, Tape and Reel
footprint SOT-23-CT5_N (SOT23, 5-Leads, Body 2.9x1.6mm, Pitch 0.95mm, Lead Span 2.7mm, IPC Medium Density)
footprint SOT-23-CT5_L (SOT23, 5-Leads, Body 2.9x1.6mm, Pitch 0.95mm, Lead Span 2.7mm, IPC High Density)
footprint SOT-23-CT5_M (SOT23, 5-Leads, Body 2.9x1.6mm, Pitch 0.95mm, Lead Span 2.7mm, IPC Low Density)
pins: 1 VIN (power), 2 GND (power), 3 ~{SHDN} (in), 4 NC, 5 VOUT (power)

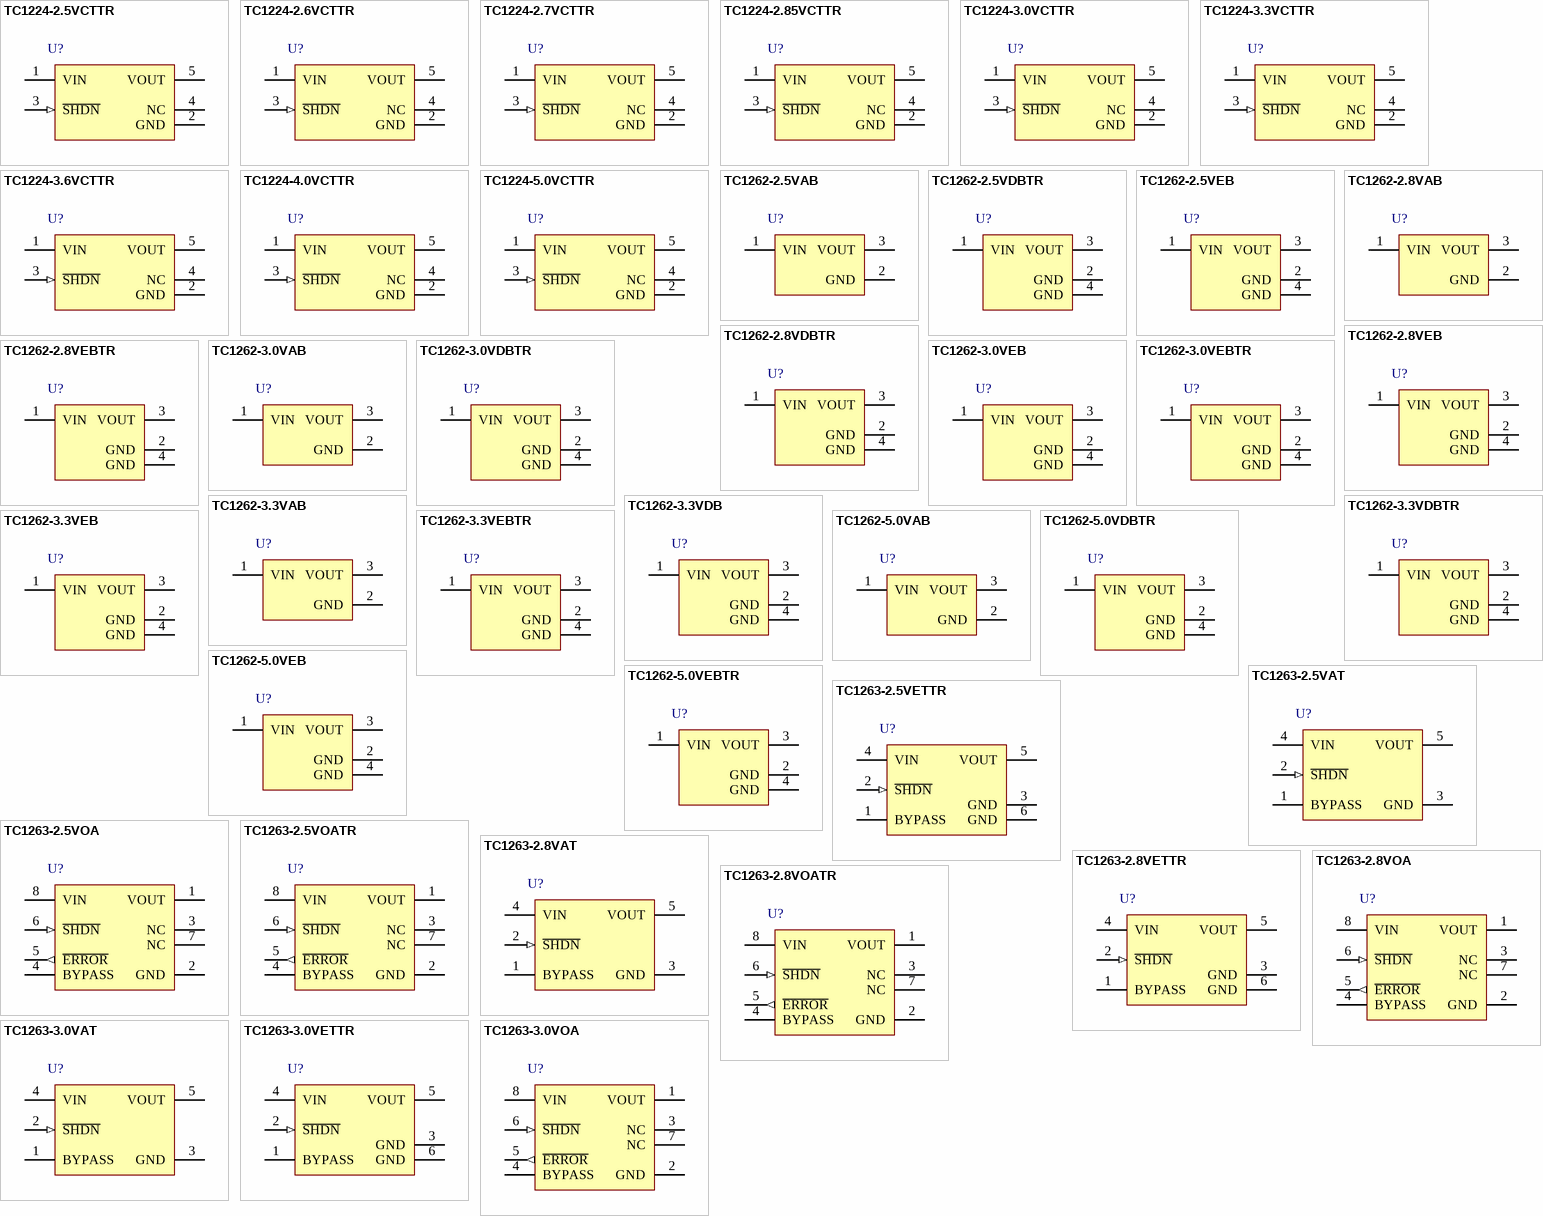
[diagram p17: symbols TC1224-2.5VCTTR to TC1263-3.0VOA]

## TC1224-2.5VCTTR
designator U?
50mA and 100mA CMOS LDOs with Shutdown, 5-Pin SOT-23, Extended Temperature, Tape and Reel
footprint SOT-23-CT5_N (SOT23, 5-Leads, Body 2.9x1.6mm, Pitch 0.95mm, Lead Span 2.7mm, IPC Medium Density)
footprint SOT-23-CT5_L (SOT23, 5-Leads, Body 2.9x1.6mm, Pitch 0.95mm, Lead Span 2.7mm, IPC High Density)
footprint SOT-23-CT5_M (SOT23, 5-Leads, Body 2.9x1.6mm, Pitch 0.95mm, Lead Span 2.7mm, IPC Low Density)
pins: 1 VIN (power), 2 GND (power), 3 ~{SHDN} (in), 4 NC, 5 VOUT (power)

## TC1224-2.6VCTTR
designator U?
50mA and 100mA CMOS LDOs with Shutdown, 5-Pin SOT-23, Extended Temperature, Tape and Reel
footprint SOT-23-CT5_N (SOT23, 5-Leads, Body 2.9x1.6mm, Pitch 0.95mm, Lead Span 2.7mm, IPC Medium Density)
footprint SOT-23-CT5_L (SOT23, 5-Leads, Body 2.9x1.6mm, Pitch 0.95mm, Lead Span 2.7mm, IPC High Density)
footprint SOT-23-CT5_M (SOT23, 5-Leads, Body 2.9x1.6mm, Pitch 0.95mm, Lead Span 2.7mm, IPC Low Density)
pins: 1 VIN (power), 2 GND (power), 3 ~{SHDN} (in), 4 NC, 5 VOUT (power)

## TC1224-2.7VCTTR
designator U?
50mA and 100mA CMOS LDOs with Shutdown, 5-Pin SOT-23, Extended Temperature, Tape and Reel
footprint SOT-23-CT5_N (SOT23, 5-Leads, Body 2.9x1.6mm, Pitch 0.95mm, Lead Span 2.7mm, IPC Medium Density)
footprint SOT-23-CT5_L (SOT23, 5-Leads, Body 2.9x1.6mm, Pitch 0.95mm, Lead Span 2.7mm, IPC High Density)
footprint SOT-23-CT5_M (SOT23, 5-Leads, Body 2.9x1.6mm, Pitch 0.95mm, Lead Span 2.7mm, IPC Low Density)
pins: 1 VIN (power), 2 GND (power), 3 ~{SHDN} (in), 4 NC, 5 VOUT (power)

## TC1224-2.85VCTTR
designator U?
50mA and 100mA CMOS LDOs with Shutdown, 5-Pin SOT-23, Extended Temperature, Tape and Reel
footprint SOT-23-CT5_N (SOT23, 5-Leads, Body 2.9x1.6mm, Pitch 0.95mm, Lead Span 2.7mm, IPC Medium Density)
footprint SOT-23-CT5_L (SOT23, 5-Leads, Body 2.9x1.6mm, Pitch 0.95mm, Lead Span 2.7mm, IPC High Density)
footprint SOT-23-CT5_M (SOT23, 5-Leads, Body 2.9x1.6mm, Pitch 0.95mm, Lead Span 2.7mm, IPC Low Density)
pins: 1 VIN (power), 2 GND (power), 3 ~{SHDN} (in), 4 NC, 5 VOUT (power)

## TC1224-3.0VCTTR
designator U?
50mA and 100mA CMOS LDOs with Shutdown, 5-Pin SOT-23, Extended Temperature, Tape and Reel
footprint SOT-23-CT5_N (SOT23, 5-Leads, Body 2.9x1.6mm, Pitch 0.95mm, Lead Span 2.7mm, IPC Medium Density)
footprint SOT-23-CT5_L (SOT23, 5-Leads, Body 2.9x1.6mm, Pitch 0.95mm, Lead Span 2.7mm, IPC High Density)
footprint SOT-23-CT5_M (SOT23, 5-Leads, Body 2.9x1.6mm, Pitch 0.95mm, Lead Span 2.7mm, IPC Low Density)
pins: 1 VIN (power), 2 GND (power), 3 ~{SHDN} (in), 4 NC, 5 VOUT (power)

## TC1224-3.3VCTTR
designator U?
50mA and 100mA CMOS LDOs with Shutdown, 5-Pin SOT-23, Extended Temperature, Tape and Reel
footprint SOT-23-CT5_N (SOT23, 5-Leads, Body 2.9x1.6mm, Pitch 0.95mm, Lead Span 2.7mm, IPC Medium Density)
footprint SOT-23-CT5_L (SOT23, 5-Leads, Body 2.9x1.6mm, Pitch 0.95mm, Lead Span 2.7mm, IPC High Density)
footprint SOT-23-CT5_M (SOT23, 5-Leads, Body 2.9x1.6mm, Pitch 0.95mm, Lead Span 2.7mm, IPC Low Density)
pins: 1 VIN (power), 2 GND (power), 3 ~{SHDN} (in), 4 NC, 5 VOUT (power)

## TC1224-3.6VCTTR
designator U?
50mA and 100mA CMOS LDOs with Shutdown, 5-Pin SOT-23, Extended Temperature, Tape and Reel
footprint SOT-23-CT5_N (SOT23, 5-Leads, Body 2.9x1.6mm, Pitch 0.95mm, Lead Span 2.7mm, IPC Medium Density)
footprint SOT-23-CT5_L (SOT23, 5-Leads, Body 2.9x1.6mm, Pitch 0.95mm, Lead Span 2.7mm, IPC High Density)
footprint SOT-23-CT5_M (SOT23, 5-Leads, Body 2.9x1.6mm, Pitch 0.95mm, Lead Span 2.7mm, IPC Low Density)
pins: 1 VIN (power), 2 GND (power), 3 ~{SHDN} (in), 4 NC, 5 VOUT (power)

## TC1224-4.0VCTTR
designator U?
50mA and 100mA CMOS LDOs with Shutdown, 5-Pin SOT-23, Extended Temperature, Tape and Reel
footprint SOT-23-CT5_N (SOT23, 5-Leads, Body 2.9x1.6mm, Pitch 0.95mm, Lead Span 2.7mm, IPC Medium Density)
footprint SOT-23-CT5_L (SOT23, 5-Leads, Body 2.9x1.6mm, Pitch 0.95mm, Lead Span 2.7mm, IPC High Density)
footprint SOT-23-CT5_M (SOT23, 5-Leads, Body 2.9x1.6mm, Pitch 0.95mm, Lead Span 2.7mm, IPC Low Density)
pins: 1 VIN (power), 2 GND (power), 3 ~{SHDN} (in), 4 NC, 5 VOUT (power)

## TC1224-5.0VCTTR
designator U?
50mA and 100mA CMOS LDOs with Shutdown, 5-Pin SOT-23, Extended Temperature, Tape and Reel
footprint SOT-23-CT5_N (SOT23, 5-Leads, Body 2.9x1.6mm, Pitch 0.95mm, Lead Span 2.7mm, IPC Medium Density)
footprint SOT-23-CT5_L (SOT23, 5-Leads, Body 2.9x1.6mm, Pitch 0.95mm, Lead Span 2.7mm, IPC High Density)
footprint SOT-23-CT5_M (SOT23, 5-Leads, Body 2.9x1.6mm, Pitch 0.95mm, Lead Span 2.7mm, IPC Low Density)
pins: 1 VIN (power), 2 GND (power), 3 ~{SHDN} (in), 4 NC, 5 VOUT (power)

## TC1262-2.5VAB
designator U?
500mA Fixed Output CMOS LDO, 3-Pin TO-220, Extended Temperature
footprint TO-220-AB3 (TO, Thru-Hole, Vertical, Heatsink Mounted; 3 In-Line Leads; Pitch 2.54 mm)
pins: 1 VIN (power), 2 GND (power), 3 VOUT (power)

## TC1262-2.5VDBTR
designator U?
500mA Fixed Output CMOS LDO, 3-Pin SOT-223, Extended Temperature, Tape and Reel
footprint SOT-223-DB3_N (SOT223, 4-Leads, Body 6.5x3.5mm, Pitch 2.3mm, Lead Span 7mm, IPC Medium Density)
footprint SOT-223-DB3_L (SOT223, 4-Leads, Body 6.5x3.5mm, Pitch 2.3mm, Lead Span 7mm, IPC High Density)
footprint SOT-223-DB3_M (SOT223, 4-Leads, Body 6.5x3.5mm, Pitch 2.3mm, Lead Span 7mm, IPC Low Density)
pins: 1 VIN (power), 2 GND (power), 3 VOUT (power), 4 GND (power)

## TC1262-2.5VEB
designator U?
500mA Fixed Output CMOS LDO, 3-Pin DDPAK, Extended Temperature
footprint DDPAK-EB3_N (D2-PAK, 4-Leads, Body 9x10.2mm, Pitch 2.54mm, Lead Span 14.9mm, IPC Medium Density)
footprint DDPAK-EB3_L (D2-PAK, 4-Leads, Body 9x10.2mm, Pitch 2.54mm, Lead Span 14.9mm, IPC High Density)
footprint DDPAK-EB3_M (D2-PAK, 4-Leads, Body 9x10.2mm, Pitch 2.54mm, Lead Span 14.9mm, IPC Low Density)
pins: 1 VIN (power), 2 GND (power), 3 VOUT (power), 4 GND (power)

## TC1262-2.8VAB
designator U?
500mA Fixed Output CMOS LDO, 3-Pin TO-220, Extended Temperature
footprint TO-220-AB3 (TO, Thru-Hole, Vertical, Heatsink Mounted; 3 In-Line Leads; Pitch 2.54 mm)
pins: 1 VIN (power), 2 GND (power), 3 VOUT (power)

## TC1262-2.8VDBTR
designator U?
500mA Fixed Output CMOS LDO, 3-Pin SOT-223, Extended Temperature, Tape and Reel
footprint SOT-223-DB3_N (SOT223, 4-Leads, Body 6.5x3.5mm, Pitch 2.3mm, Lead Span 7mm, IPC Medium Density)
footprint SOT-223-DB3_L (SOT223, 4-Leads, Body 6.5x3.5mm, Pitch 2.3mm, Lead Span 7mm, IPC High Density)
footprint SOT-223-DB3_M (SOT223, 4-Leads, Body 6.5x3.5mm, Pitch 2.3mm, Lead Span 7mm, IPC Low Density)
pins: 1 VIN (power), 2 GND (power), 3 VOUT (power), 4 GND (power)

## TC1262-2.8VEB
designator U?
500mA Fixed Output CMOS LDO, 3-Pin DDPAK, Extended Temperature
footprint DDPAK-EB3_N (D2-PAK, 4-Leads, Body 9x10.2mm, Pitch 2.54mm, Lead Span 14.9mm, IPC Medium Density)
footprint DDPAK-EB3_L (D2-PAK, 4-Leads, Body 9x10.2mm, Pitch 2.54mm, Lead Span 14.9mm, IPC High Density)
footprint DDPAK-EB3_M (D2-PAK, 4-Leads, Body 9x10.2mm, Pitch 2.54mm, Lead Span 14.9mm, IPC Low Density)
pins: 1 VIN (power), 2 GND (power), 3 VOUT (power), 4 GND (power)

## TC1262-2.8VEBTR
designator U?
500mA Fixed Output CMOS LDO, 3-Pin DDPAK, Extended Temperature, Tape and Reel
footprint DDPAK-EB3_N (D2-PAK, 4-Leads, Body 9x10.2mm, Pitch 2.54mm, Lead Span 14.9mm, IPC Medium Density)
footprint DDPAK-EB3_L (D2-PAK, 4-Leads, Body 9x10.2mm, Pitch 2.54mm, Lead Span 14.9mm, IPC High Density)
footprint DDPAK-EB3_M (D2-PAK, 4-Leads, Body 9x10.2mm, Pitch 2.54mm, Lead Span 14.9mm, IPC Low Density)
pins: 1 VIN (power), 2 GND (power), 3 VOUT (power), 4 GND (power)

## TC1262-3.0VAB
designator U?
500mA Fixed Output CMOS LDO, 3-Pin TO-220, Extended Temperature
footprint TO-220-AB3 (TO, Thru-Hole, Vertical, Heatsink Mounted; 3 In-Line Leads; Pitch 2.54 mm)
pins: 1 VIN (power), 2 GND (power), 3 VOUT (power)

## TC1262-3.0VDBTR
designator U?
500mA Fixed Output CMOS LDO, 3-Pin SOT-223, Extended Temperature, Tape and Reel
footprint SOT-223-DB3_N (SOT223, 4-Leads, Body 6.5x3.5mm, Pitch 2.3mm, Lead Span 7mm, IPC Medium Density)
footprint SOT-223-DB3_L (SOT223, 4-Leads, Body 6.5x3.5mm, Pitch 2.3mm, Lead Span 7mm, IPC High Density)
footprint SOT-223-DB3_M (SOT223, 4-Leads, Body 6.5x3.5mm, Pitch 2.3mm, Lead Span 7mm, IPC Low Density)
pins: 1 VIN (power), 2 GND (power), 3 VOUT (power), 4 GND (power)

## TC1262-3.0VEB
designator U?
500mA Fixed Output CMOS LDO, 3-Pin DDPAK, Extended Temperature
footprint DDPAK-EB3_N (D2-PAK, 4-Leads, Body 9x10.2mm, Pitch 2.54mm, Lead Span 14.9mm, IPC Medium Density)
footprint DDPAK-EB3_L (D2-PAK, 4-Leads, Body 9x10.2mm, Pitch 2.54mm, Lead Span 14.9mm, IPC High Density)
footprint DDPAK-EB3_M (D2-PAK, 4-Leads, Body 9x10.2mm, Pitch 2.54mm, Lead Span 14.9mm, IPC Low Density)
pins: 1 VIN (power), 2 GND (power), 3 VOUT (power), 4 GND (power)

## TC1262-3.0VEBTR
designator U?
500mA Fixed Output CMOS LDO, 3-Pin DDPAK, Extended Temperature, Tape and Reel
footprint DDPAK-EB3_N (D2-PAK, 4-Leads, Body 9x10.2mm, Pitch 2.54mm, Lead Span 14.9mm, IPC Medium Density)
footprint DDPAK-EB3_L (D2-PAK, 4-Leads, Body 9x10.2mm, Pitch 2.54mm, Lead Span 14.9mm, IPC High Density)
footprint DDPAK-EB3_M (D2-PAK, 4-Leads, Body 9x10.2mm, Pitch 2.54mm, Lead Span 14.9mm, IPC Low Density)
pins: 1 VIN (power), 2 GND (power), 3 VOUT (power), 4 GND (power)

## TC1262-3.3VAB
designator U?
500mA Fixed Output CMOS LDO, 3-Pin TO-220, Extended Temperature
footprint TO-220-AB3 (TO, Thru-Hole, Vertical, Heatsink Mounted; 3 In-Line Leads; Pitch 2.54 mm)
pins: 1 VIN (power), 2 GND (power), 3 VOUT (power)

## TC1262-3.3VDB
designator U?
500mA Fixed Output CMOS LDO, 3-Pin SOT-223, Extended Temperature
footprint SOT-223-DB3_N (SOT223, 4-Leads, Body 6.5x3.5mm, Pitch 2.3mm, Lead Span 7mm, IPC Medium Density)
footprint SOT-223-DB3_L (SOT223, 4-Leads, Body 6.5x3.5mm, Pitch 2.3mm, Lead Span 7mm, IPC High Density)
footprint SOT-223-DB3_M (SOT223, 4-Leads, Body 6.5x3.5mm, Pitch 2.3mm, Lead Span 7mm, IPC Low Density)
pins: 1 VIN (power), 2 GND (power), 3 VOUT (power), 4 GND (power)

## TC1262-3.3VDBTR
designator U?
500mA Fixed Output CMOS LDO, 3-Pin SOT-223, Extended Temperature, Tape and Reel
footprint SOT-223-DB3_N (SOT223, 4-Leads, Body 6.5x3.5mm, Pitch 2.3mm, Lead Span 7mm, IPC Medium Density)
footprint SOT-223-DB3_L (SOT223, 4-Leads, Body 6.5x3.5mm, Pitch 2.3mm, Lead Span 7mm, IPC High Density)
footprint SOT-223-DB3_M (SOT223, 4-Leads, Body 6.5x3.5mm, Pitch 2.3mm, Lead Span 7mm, IPC Low Density)
pins: 1 VIN (power), 2 GND (power), 3 VOUT (power), 4 GND (power)

## TC1262-3.3VEB
designator U?
500mA Fixed Output CMOS LDO, 3-Pin DDPAK, Extended Temperature
footprint DDPAK-EB3_N (D2-PAK, 4-Leads, Body 9x10.2mm, Pitch 2.54mm, Lead Span 14.9mm, IPC Medium Density)
footprint DDPAK-EB3_L (D2-PAK, 4-Leads, Body 9x10.2mm, Pitch 2.54mm, Lead Span 14.9mm, IPC High Density)
footprint DDPAK-EB3_M (D2-PAK, 4-Leads, Body 9x10.2mm, Pitch 2.54mm, Lead Span 14.9mm, IPC Low Density)
pins: 1 VIN (power), 2 GND (power), 3 VOUT (power), 4 GND (power)

## TC1262-3.3VEBTR
designator U?
500mA Fixed Output CMOS LDO, 3-Pin DDPAK, Extended Temperature, Tape and Reel
footprint DDPAK-EB3_N (D2-PAK, 4-Leads, Body 9x10.2mm, Pitch 2.54mm, Lead Span 14.9mm, IPC Medium Density)
footprint DDPAK-EB3_L (D2-PAK, 4-Leads, Body 9x10.2mm, Pitch 2.54mm, Lead Span 14.9mm, IPC High Density)
footprint DDPAK-EB3_M (D2-PAK, 4-Leads, Body 9x10.2mm, Pitch 2.54mm, Lead Span 14.9mm, IPC Low Density)
pins: 1 VIN (power), 2 GND (power), 3 VOUT (power), 4 GND (power)

## TC1262-5.0VAB
designator U?
500mA Fixed Output CMOS LDO, 3-Pin TO-220, Extended Temperature
footprint TO-220-AB3 (TO, Thru-Hole, Vertical, Heatsink Mounted; 3 In-Line Leads; Pitch 2.54 mm)
pins: 1 VIN (power), 2 GND (power), 3 VOUT (power)

## TC1262-5.0VDBTR
designator U?
500mA Fixed Output CMOS LDO, 3-Pin SOT-223, Extended Temperature, Tape and Reel
footprint SOT-223-DB3_N (SOT223, 4-Leads, Body 6.5x3.5mm, Pitch 2.3mm, Lead Span 7mm, IPC Medium Density)
footprint SOT-223-DB3_L (SOT223, 4-Leads, Body 6.5x3.5mm, Pitch 2.3mm, Lead Span 7mm, IPC High Density)
footprint SOT-223-DB3_M (SOT223, 4-Leads, Body 6.5x3.5mm, Pitch 2.3mm, Lead Span 7mm, IPC Low Density)
pins: 1 VIN (power), 2 GND (power), 3 VOUT (power), 4 GND (power)

## TC1262-5.0VEB
designator U?
500mA Fixed Output CMOS LDO, 3-Pin DDPAK, Extended Temperature
footprint DDPAK-EB3_N (D2-PAK, 4-Leads, Body 9x10.2mm, Pitch 2.54mm, Lead Span 14.9mm, IPC Medium Density)
footprint DDPAK-EB3_L (D2-PAK, 4-Leads, Body 9x10.2mm, Pitch 2.54mm, Lead Span 14.9mm, IPC High Density)
footprint DDPAK-EB3_M (D2-PAK, 4-Leads, Body 9x10.2mm, Pitch 2.54mm, Lead Span 14.9mm, IPC Low Density)
pins: 1 VIN (power), 2 GND (power), 3 VOUT (power), 4 GND (power)

## TC1262-5.0VEBTR
designator U?
500mA Fixed Output CMOS LDO, 3-Pin DDPAK, Extended Temperature, Tape and Reel
footprint DDPAK-EB3_N (D2-PAK, 4-Leads, Body 9x10.2mm, Pitch 2.54mm, Lead Span 14.9mm, IPC Medium Density)
footprint DDPAK-EB3_L (D2-PAK, 4-Leads, Body 9x10.2mm, Pitch 2.54mm, Lead Span 14.9mm, IPC High Density)
footprint DDPAK-EB3_M (D2-PAK, 4-Leads, Body 9x10.2mm, Pitch 2.54mm, Lead Span 14.9mm, IPC Low Density)
pins: 1 VIN (power), 2 GND (power), 3 VOUT (power), 4 GND (power)

## TC1263-2.5VAT
designator U?
500mA Fixed Output, CMOS LDO with Shutdown, 5-Pin TO-220, Extended Temperature
footprint TO-220-AT5 (TO, Thru-Hole, Vertical, Heatsink Mounted; 5 In-Line Leads; Pitch 1.70 mm)
pins: 1 BYPASS, 2 ~{SHDN} (in), 3 GND (power), 4 VIN (power), 5 VOUT (power)

## TC1263-2.5VETTR
designator U?
500mA Fixed Output, CMOS LDO with Shutdown, 5-Pin DDPAK, Extended Temperature, Tape and Reel
footprint DDPAK-ET5_N (D2-PAK, 6-Leads, Body 9x10.2mm, Pitch 1.7mm, Lead Span 14.9mm, IPC Medium Density)
footprint DDPAK-ET5_L (D2-PAK, 6-Leads, Body 9x10.2mm, Pitch 1.7mm, Lead Span 14.9mm, IPC High Density)
footprint DDPAK-ET5_M (D2-PAK, 6-Leads, Body 9x10.2mm, Pitch 1.7mm, Lead Span 14.9mm, IPC Low Density)
pins: 1 BYPASS, 2 ~{SHDN} (in), 3 GND (power), 4 VIN (power), 5 VOUT (power), 6 GND (power)

## TC1263-2.5VOA
designator U?
500mA Fixed Output, CMOS LDO with Shutdown, 8-Pin SOIC 150mil, Extended Temperature
footprint SOIC-OA8_N (SOIC, 8-Leads, Body 4.9x3.9mm, Pitch 1.27mm, IPC Medium Density)
footprint SOIC-OA8_L (SOIC, 8-Leads, Body 4.9x3.9mm, Pitch 1.27mm, IPC High Density)
footprint SOIC-OA8_M (SOIC, 8-Leads, Body 4.9x3.9mm, Pitch 1.27mm, IPC Low Density)
pins: 1 VOUT (power), 2 GND (power), 3 NC, 4 BYPASS, 5 ~{ERROR} (out), 6 ~{SHDN} (in), 7 NC, 8 VIN (power)

## TC1263-2.5VOATR
designator U?
500mA Fixed Output, CMOS LDO with Shutdown, 8-Pin SOIC 150mil, Extended Temperature, Tape and Reel
footprint SOIC-OA8_N (SOIC, 8-Leads, Body 4.9x3.9mm, Pitch 1.27mm, IPC Medium Density)
footprint SOIC-OA8_L (SOIC, 8-Leads, Body 4.9x3.9mm, Pitch 1.27mm, IPC High Density)
footprint SOIC-OA8_M (SOIC, 8-Leads, Body 4.9x3.9mm, Pitch 1.27mm, IPC Low Density)
pins: 1 VOUT (power), 2 GND (power), 3 NC, 4 BYPASS, 5 ~{ERROR} (out), 6 ~{SHDN} (in), 7 NC, 8 VIN (power)

## TC1263-2.8VAT
designator U?
500mA Fixed Output, CMOS LDO with Shutdown, 5-Pin TO-220, Extended Temperature
footprint TO-220-AT5 (TO, Thru-Hole, Vertical, Heatsink Mounted; 5 In-Line Leads; Pitch 1.70 mm)
pins: 1 BYPASS, 2 ~{SHDN} (in), 3 GND (power), 4 VIN (power), 5 VOUT (power)

## TC1263-2.8VETTR
designator U?
500mA Fixed Output, CMOS LDO with Shutdown, 5-Pin DDPAK, Extended Temperature, Tape and Reel
footprint DDPAK-ET5_N (D2-PAK, 6-Leads, Body 9x10.2mm, Pitch 1.7mm, Lead Span 14.9mm, IPC Medium Density)
footprint DDPAK-ET5_L (D2-PAK, 6-Leads, Body 9x10.2mm, Pitch 1.7mm, Lead Span 14.9mm, IPC High Density)
footprint DDPAK-ET5_M (D2-PAK, 6-Leads, Body 9x10.2mm, Pitch 1.7mm, Lead Span 14.9mm, IPC Low Density)
pins: 1 BYPASS, 2 ~{SHDN} (in), 3 GND (power), 4 VIN (power), 5 VOUT (power), 6 GND (power)

## TC1263-2.8VOA
designator U?
500mA Fixed Output, CMOS LDO with Shutdown, 8-Pin SOIC 150mil, Extended Temperature
footprint SOIC-OA8_N (SOIC, 8-Leads, Body 4.9x3.9mm, Pitch 1.27mm, IPC Medium Density)
footprint SOIC-OA8_L (SOIC, 8-Leads, Body 4.9x3.9mm, Pitch 1.27mm, IPC High Density)
footprint SOIC-OA8_M (SOIC, 8-Leads, Body 4.9x3.9mm, Pitch 1.27mm, IPC Low Density)
pins: 1 VOUT (power), 2 GND (power), 3 NC, 4 BYPASS, 5 ~{ERROR} (out), 6 ~{SHDN} (in), 7 NC, 8 VIN (power)

## TC1263-2.8VOATR
designator U?
500mA Fixed Output, CMOS LDO with Shutdown, 8-Pin SOIC 150mil, Extended Temperature, Tape and Reel
footprint SOIC-OA8_N (SOIC, 8-Leads, Body 4.9x3.9mm, Pitch 1.27mm, IPC Medium Density)
footprint SOIC-OA8_L (SOIC, 8-Leads, Body 4.9x3.9mm, Pitch 1.27mm, IPC High Density)
footprint SOIC-OA8_M (SOIC, 8-Leads, Body 4.9x3.9mm, Pitch 1.27mm, IPC Low Density)
pins: 1 VOUT (power), 2 GND (power), 3 NC, 4 BYPASS, 5 ~{ERROR} (out), 6 ~{SHDN} (in), 7 NC, 8 VIN (power)

## TC1263-3.0VAT
designator U?
500mA Fixed Output, CMOS LDO with Shutdown, 5-Pin TO-220, Extended Temperature
footprint TO-220-AT5 (TO, Thru-Hole, Vertical, Heatsink Mounted; 5 In-Line Leads; Pitch 1.70 mm)
pins: 1 BYPASS, 2 ~{SHDN} (in), 3 GND (power), 4 VIN (power), 5 VOUT (power)

## TC1263-3.0VETTR
designator U?
500mA Fixed Output, CMOS LDO with Shutdown, 5-Pin DDPAK, Extended Temperature, Tape and Reel
footprint DDPAK-ET5_N (D2-PAK, 6-Leads, Body 9x10.2mm, Pitch 1.7mm, Lead Span 14.9mm, IPC Medium Density)
footprint DDPAK-ET5_L (D2-PAK, 6-Leads, Body 9x10.2mm, Pitch 1.7mm, Lead Span 14.9mm, IPC High Density)
footprint DDPAK-ET5_M (D2-PAK, 6-Leads, Body 9x10.2mm, Pitch 1.7mm, Lead Span 14.9mm, IPC Low Density)
pins: 1 BYPASS, 2 ~{SHDN} (in), 3 GND (power), 4 VIN (power), 5 VOUT (power), 6 GND (power)

## TC1263-3.0VOA
designator U?
500mA Fixed Output, CMOS LDO with Shutdown, 8-Pin SOIC 150mil, Extended Temperature
footprint SOIC-OA8_N (SOIC, 8-Leads, Body 4.9x3.9mm, Pitch 1.27mm, IPC Medium Density)
footprint SOIC-OA8_L (SOIC, 8-Leads, Body 4.9x3.9mm, Pitch 1.27mm, IPC High Density)
footprint SOIC-OA8_M (SOIC, 8-Leads, Body 4.9x3.9mm, Pitch 1.27mm, IPC Low Density)
pins: 1 VOUT (power), 2 GND (power), 3 NC, 4 BYPASS, 5 ~{ERROR} (out), 6 ~{SHDN} (in), 7 NC, 8 VIN (power)

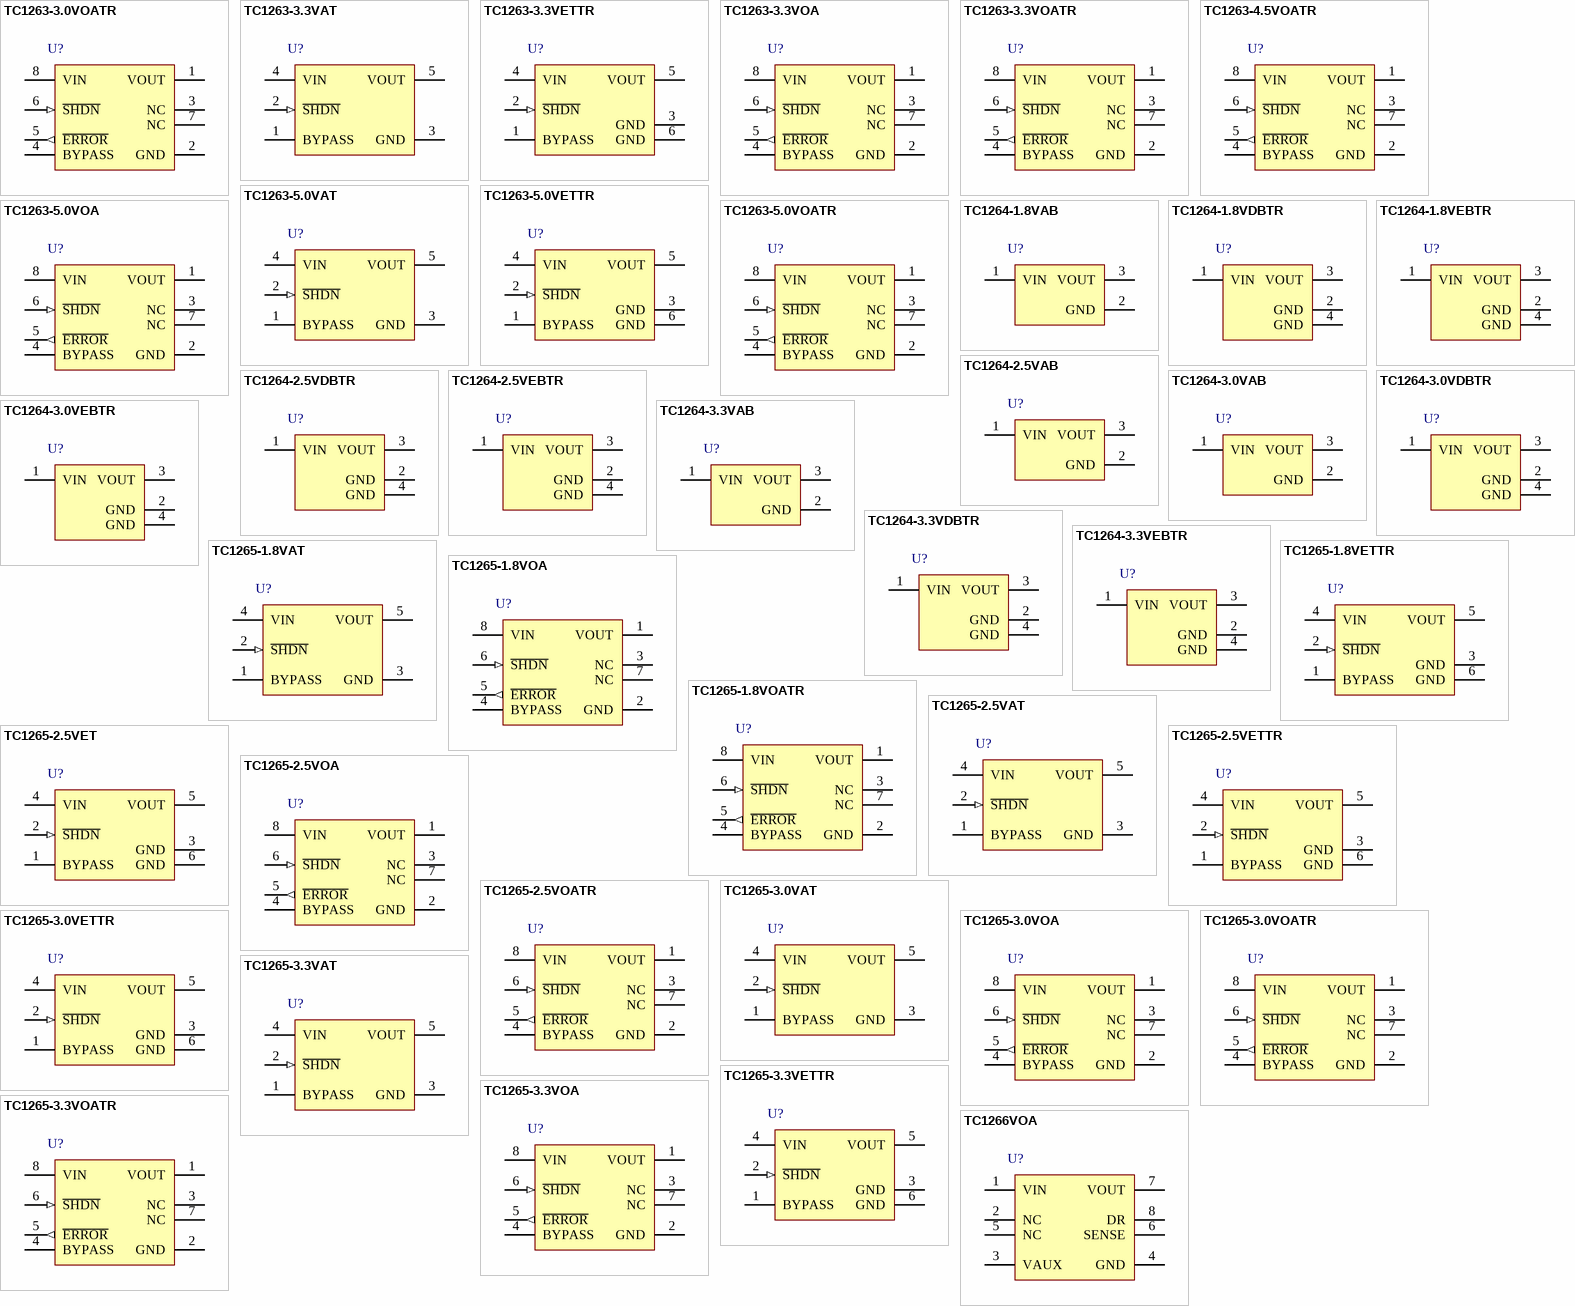
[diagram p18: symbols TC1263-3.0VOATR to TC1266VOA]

## TC1263-3.0VOATR
designator U?
500mA Fixed Output, CMOS LDO with Shutdown, 8-Pin SOIC 150mil, Extended Temperature, Tape and Reel
footprint SOIC-OA8_N (SOIC, 8-Leads, Body 4.9x3.9mm, Pitch 1.27mm, IPC Medium Density)
footprint SOIC-OA8_L (SOIC, 8-Leads, Body 4.9x3.9mm, Pitch 1.27mm, IPC High Density)
footprint SOIC-OA8_M (SOIC, 8-Leads, Body 4.9x3.9mm, Pitch 1.27mm, IPC Low Density)
pins: 1 VOUT (power), 2 GND (power), 3 NC, 4 BYPASS, 5 ~{ERROR} (out), 6 ~{SHDN} (in), 7 NC, 8 VIN (power)

## TC1263-3.3VAT
designator U?
500mA Fixed Output, CMOS LDO with Shutdown, 5-Pin TO-220, Extended Temperature
footprint TO-220-AT5 (TO, Thru-Hole, Vertical, Heatsink Mounted; 5 In-Line Leads; Pitch 1.70 mm)
pins: 1 BYPASS, 2 ~{SHDN} (in), 3 GND (power), 4 VIN (power), 5 VOUT (power)

## TC1263-3.3VETTR
designator U?
500mA Fixed Output, CMOS LDO with Shutdown, 5-Pin DDPAK, Extended Temperature, Tape and Reel
footprint DDPAK-ET5_N (D2-PAK, 6-Leads, Body 9x10.2mm, Pitch 1.7mm, Lead Span 14.9mm, IPC Medium Density)
footprint DDPAK-ET5_L (D2-PAK, 6-Leads, Body 9x10.2mm, Pitch 1.7mm, Lead Span 14.9mm, IPC High Density)
footprint DDPAK-ET5_M (D2-PAK, 6-Leads, Body 9x10.2mm, Pitch 1.7mm, Lead Span 14.9mm, IPC Low Density)
pins: 1 BYPASS, 2 ~{SHDN} (in), 3 GND (power), 4 VIN (power), 5 VOUT (power), 6 GND (power)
